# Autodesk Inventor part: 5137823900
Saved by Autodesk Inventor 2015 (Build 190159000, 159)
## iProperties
Created: 2020-07
Part Number: 5137823900
Checked By: TraceParts S.A.
Material: Generic
Catalog Web Link: www.traceparts.com
Document SubType Name: Modeling
Designer: TraceParts
Density: 1 g/cm^3
Appearance: Default
Company: TraceParts S.A.
Author: TraceParts
REFERENCE: 5137823900
DESIGN: CVAT/4-3000/355 N D PTC 0,18KW (230/400V) 50HZ - 5137823900
SUPPLIER: Soler & Palau
TraceParts.PartNumber: 10-14122018-105188
TraceParts.PartTitle: CVAT-N
TraceParts.InstanceId: 10-14122018-105188256YMX116I1OCK3PNVSSG1CT3
TraceParts.PartStatus: Published
TraceParts.PartVersion: 1.0.4
TRACEPARTS: TRACEPARTS
TraceParts.PartLanguage: en
TraceParts.ClassPath: SOLER_PALAU:10-14122018-105188
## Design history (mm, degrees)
feature "5137823900"
body "Solid1"
